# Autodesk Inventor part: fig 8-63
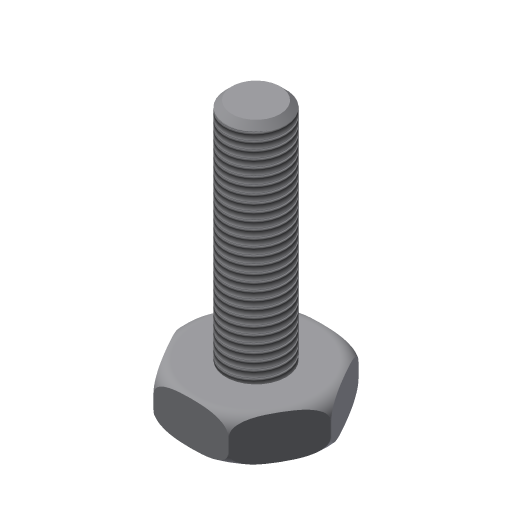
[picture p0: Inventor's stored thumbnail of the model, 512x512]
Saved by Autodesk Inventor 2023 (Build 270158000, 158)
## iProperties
Created: 2002-01
Part Number: fig 8-63
Document SubType Name: Modeling
Designer: ***
Density: 1 g/cm^3
Material: Generic
Appearance: Default
Control State: 0
Master: False
Checked Out: False
Shininess: 77.0
Length Units: 11269
Angle Units: 11279
Time Units: 11290
Mass Units: 11283
Length Display Precision: 3
Angle Display Precision: 2
Density: 0.0
Volumn: 0.0
Area: 0.0
PropertySet Name: Model Information
Author: ***
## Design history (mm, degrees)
sketch "Sketch1"
  geometry: C1 r 25 at (0, 0)
  constraints: 1 centre point
  dimensions: "d0" = 50 diameter of C1
extrude "Extrusion1" new body sketch "Sketch1" distance "d1" = 15; taper "d2" = 0 deg
fillet "Fillet1" dims "d3" = 5
sketch "Sketch2"
  geometry: L1 (25.058, 0)-(12.529, -21.701); L2 (12.529, -21.701)-(-12.529, -21.701); L3 (-12.529, -21.701)-(-25.058, 0); L4 (-25.058, 0)-(-12.529, 21.701); L5 (-12.529, 21.701)-(12.529, 21.701); L6 (12.529, 21.701)-(25.058, 0); 1 further point
  constraints: 12 end point, 11 other
extrude "Extrusion2" sketch "Sketch2" extent not by distance; stored distance "d4" = 15; taper "d5" = 0 deg
sketch "Sketch3"
  geometry: C1 r 10.044 at (0, 0); 1 further point
  constraints: 1 centre point, 1 coincident
extrude "Extrusion3" join sketch "Sketch3" distance "d6" = 75; taper "d7" = 0 deg
chamfer "Chamfer1" distance "d8" = 2; stored, may be unused: second distance "d9" = 2, angle "d16" = 45 deg
thread "Thread3" dims "d14" = 30, "d15" = 0
body "Solid1"
